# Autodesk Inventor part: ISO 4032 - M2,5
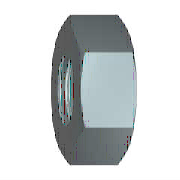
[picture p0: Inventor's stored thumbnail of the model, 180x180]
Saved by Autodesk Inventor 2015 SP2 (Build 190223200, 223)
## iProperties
Created: 2012-02
Part Number: ISO 4032 - M2,5
Material: Edelstahl, 440C
Description: Sechskantmuttern, Typ 1 - Produktklasse A und B
Document SubType Name: Modeling
Standard: ISO 4032
Designer: rYan
Standard Revision: Third edition 1999-08-15
Standards Organization: ISO
Language: de-DE
Size Designation: M2,5
Categories: <MemberInstance><Categories><Category DisplayName="Verbindungselemente" InternalName="e4da775c-781d-43d5-af7c-5136215cf5a6" Mnemonic="FSTN"><Category DisplayNam
Density: 7.75 g/cm^3
Appearance: Halbpoliert
IsCustomPart: 0
Author: rYan
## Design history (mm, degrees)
sketch "Skizze1"
  geometry: L1 (-2.887, 0)-(-1.443, 2.5); L2 (-1.443, 2.5)-(1.443, 2.5); L3 (1.443, 2.5)-(2.887, 0); L4 (2.887, 0)-(1.443, -2.5); L5 (1.443, -2.5)-(-1.443, -2.5); L6 (-1.443, -2.5)-(-2.887, 0); 2 further points
  constraints: 12 end point, 1 coincident, 1 horizontal, 11 other
  dimensions: "d0" = 5.7735 distance of L3.end L1.start (= 1.1547 x SW)
extrude "Körper" new body sketch "Skizze1" distance "d1" = 2 (= KOH); taper "d2" = 0 deg
sketch "Skizze2"
  geometry: L1 (0, 1.443)-(0, 2.887) reference; L2 (0, 2.887)-(2, 2.887) reference; L3 (2, 1.443)-(2, 2.887) reference; L4 (-0.4, 0)-(2.4, 0) reference; L5 (0.483, 2.887)-(0, 2.05); L6 (1.517, 2.887)-(2, 2.05)
  constraints: 4 end point, 4 point on line
  dimensions: "d3" = 30 deg angle of L1 L5 (= ANG1); "d4" = 30 deg angle of L3 L6 (= ANG2); "d5" = 4.1 diameter of L5.end L4 (= SW0); "d6" = 4.1 diameter of L6.end L4 (= SW01)
revolve "Fase1" sketch "Skizze2" stored, may be unused: angle "d7" = 90 deg
sketch "Skizze3"
  geometry: 4 further points
  constraints: 1 coincident, 1 other
hole "Gewinde" sketch "Skizze3" at (0, 0) diameter "d25" = 2.013; stored, may be unused: countersink angle "d29" = 82 deg, drill point angle "d31" = 118 deg; dims "d26" = 6, "d27" = 4, "d28" = 2, "d30" = 8
workaxis "Work Axis1"
workplane "Work Plane1"
body "Solid1"
chamfer "Fase2" distance "d8" = 0.24357 (= -0.5 x GD1 + 0.5 x NND); stored, may be unused: angle "d9" = 30 deg, second distance "d40" = 0.24357 (= -0.5 x GD1 + 0.5 x NND)
chamfer "Fase3" distance "d10" = 0.24357 (= -0.5 x GD1 + 0.5 x NND); stored, may be unused: angle "d11" = 30 deg, second distance "d41" = 0.24357 (= -0.5 x GD1 + 0.5 x NND)
other parameters: "ANG1" = 30 deg [user parameter; used in 1 equation term], "ANG2" = 30 deg [user parameter; used in 1 equation term], "NND" = 2.5 [user parameter; used in 4 equation terms], "KOH" = 2 [user parameter; used in 1 equation term], "SW" = 5 [user parameter; used in 2 equation terms], "SW0" = 4.1 [user parameter; used in 2 equation terms], "SW01" = 4.1 (= SW0) [user parameter; used in 1 equation term], "GD1" = 2.01286 (computed from THREADDIA, PTC, TOA) [user parameter; used in 4 equation terms], "d13" = 0, "d14" = 0, "d39" = 0, "d42" = 0, "GUL" = 0.24357 (= 0.541266 x PTC) [user parameter], "TPU" = 22.22222 (computed from PTC) [user parameter], "THREADDIA" = 2.5 [user parameter; used in 1 equation term], "TOA" = 30 deg [user parameter; used in 1 equation term], "PTC" = 0.45 [user parameter; used in 4 equation terms], "E0" = 5.775 (= 1.155 x SW) [user parameter], "GAL" = 0.24357 (= 0.541266 x PTC) [user parameter]
